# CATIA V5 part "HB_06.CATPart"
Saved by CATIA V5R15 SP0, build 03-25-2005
Part number: HB_06
Material "Dark Yellow": density 7860 kg/m3, Young's modulus 2e+11 Pa, Poisson ratio 0.266
Bounding box of the stored display mesh (mm): x -79 to 0, y 0 to 474, z 0 to 113.2
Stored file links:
  E:\#01 CATIA Lecture Materials\#06 DMU\#11 DMU Page01 KIN EX11\HB_06.CATPart
  E:\공학과제\HB-16.CATPart
  C:\Program Files\Dassault Systemes\B20\win_b64\startup\materials\Catalog.CATMaterial
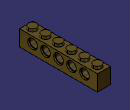
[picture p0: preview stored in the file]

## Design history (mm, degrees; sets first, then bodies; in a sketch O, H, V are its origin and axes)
Body1 (main body), material "Dark Yellow"
  Sketch1 on xy-plane, origin (0, 0, 0), H (1, 0, 0), V (0, 1, 0)
    circle A1 centre (-39.5, 39.5) radius 24.5
    point P1 (-39.5, 39.5)
    reference projected line E1 (0, 0) -> (0, 1264)
    reference projected line E2 (-79, 0) -> (-79, 1264)
    reference projected line E3 (-79, 0) -> (0, 0)
    radius A1 = 24.5
    distance P1 E3 = 39.5
    equidistance: E1 E2 P1
  Pad1: profile Sketch1, direction (0, 0, 1), length 113.2
  RectPattern1: of the body so far, direction 1 instances 6, spacing 79, along yz-plane
  Sketch2 on zx-plane, origin (0, 0, 0), H (-1, 0, 0), V (0, 0, 1)
    point P1 (0, 96)
    line L1 (0, 96) -> (79, 96)
    line L2 (79, 96) -> (79, 0)
    line L3 (79, 0) -> (0, 0)
    line L4 (0, 0) -> (0, 96)
    point P3 (79, 0)
    distance L2 L4 = 79
    length L2 = 96
    coincidence: P1 V, P3 H
    horizontal: L1 H, L3 H
    vertical: L2 V, L4 V
  Pad2: profile Sketch2, direction (0, 1, 0), length 474 {= RectPattern1.Nb1 * (79*1mm)}
  Plane1: type Offset, RefPlane zx-plane, Offset 79
  Sketch3 on Plane1, origin (0, 79, 0), H (-1, 0, 0), V (0, 0, 1)
    axis line L1 (95.3003, 56) -> (-23.8651, 56)
    reference projected line E1 (79, 96) -> (0, 96) from edge [start face of Pad2 | face of Pad2 from Sketch2.L1]
    point P3 (79, 56)
    line L2 (79, 56) -> (79, 85.25)
    line L3 (79, 85.25) -> (70, 85.25)
    line L4 (70, 85.25) -> (70, 80.25)
    line L5 (70, 80.25) -> (9, 80.25)
    line L6 (9, 80.25) -> (9, 85.25)
    point P8 (9, 85.25)
    line L7 (9, 85.25) -> (0, 85.25)
    point P9 (0, 85.25)
    line L8 (0, 85.25) -> (0, 56)
    point P10 (0, 56)
    reference projected line E2 (79, 0) -> (79, 96) from edge [start face of Pad2 | face of Pad2 from Sketch2.L2]
    distance L1 E1 = 40
    distance L8 L6 = 9
    distance L4 L2 = 9
    distance L5 L1 = 24.25
    distance L7 L1 = 29.25
    horizontal: L1 H, L3 H, L5 H, L7 H
    coincidence: P3 L1, P8 L3, P9 V, P10 L1, L2 E2
    vertical: L2 V, L4 V, L6 V, L8 V
  Groove1: profile Sketch3, axis Sketch3.L1, angle 360
  RectPattern2: of Groove1, direction 1 instances 5 {= RectPattern1.Nb1 - 1}, spacing 79, along edge [face of Pad2 from Sketch2.L4 | face of Pad2 from Sketch2.L1]
  Shell1: ExtOffset 0, Face face of Pad2, IntOffset 10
